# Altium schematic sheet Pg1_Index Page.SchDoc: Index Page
size 431 x 279 mm; Date: Not shown in title block; ApprovedBy: Not shown in title block; CheckedBy: Not shown in title block; Author: Not shown in title block; CompanyName: Not shown in title block; Engineer: Not shown in title block; Organization: Not shown in title block; Address1: Not shown in title block; Address2: Not shown in title block; Address3: Not shown in title block; Address4: Not shown in title block; DocumentNumber: 1; Revision: Use project parameter SCH_Rev; SheetNumber: 1; SheetTotal: 9; PageSetup: Record=PageOptions|CenterHorizontal=True|CenterVertical=True|PrintScale=1.00|XCorrection=1.00|YCorrection=1.00|PrintKind=0|BorderSize=5000000|LeftOffset=0|BottomOffset=0|Orientation=2|PaperLength=1000|PaperWidth=1000|Scale=100|PaperSource=15|PrintQuality=600|MediaType=1|DitherType=10|PaperKind=Letter|PrintScaleMode=1
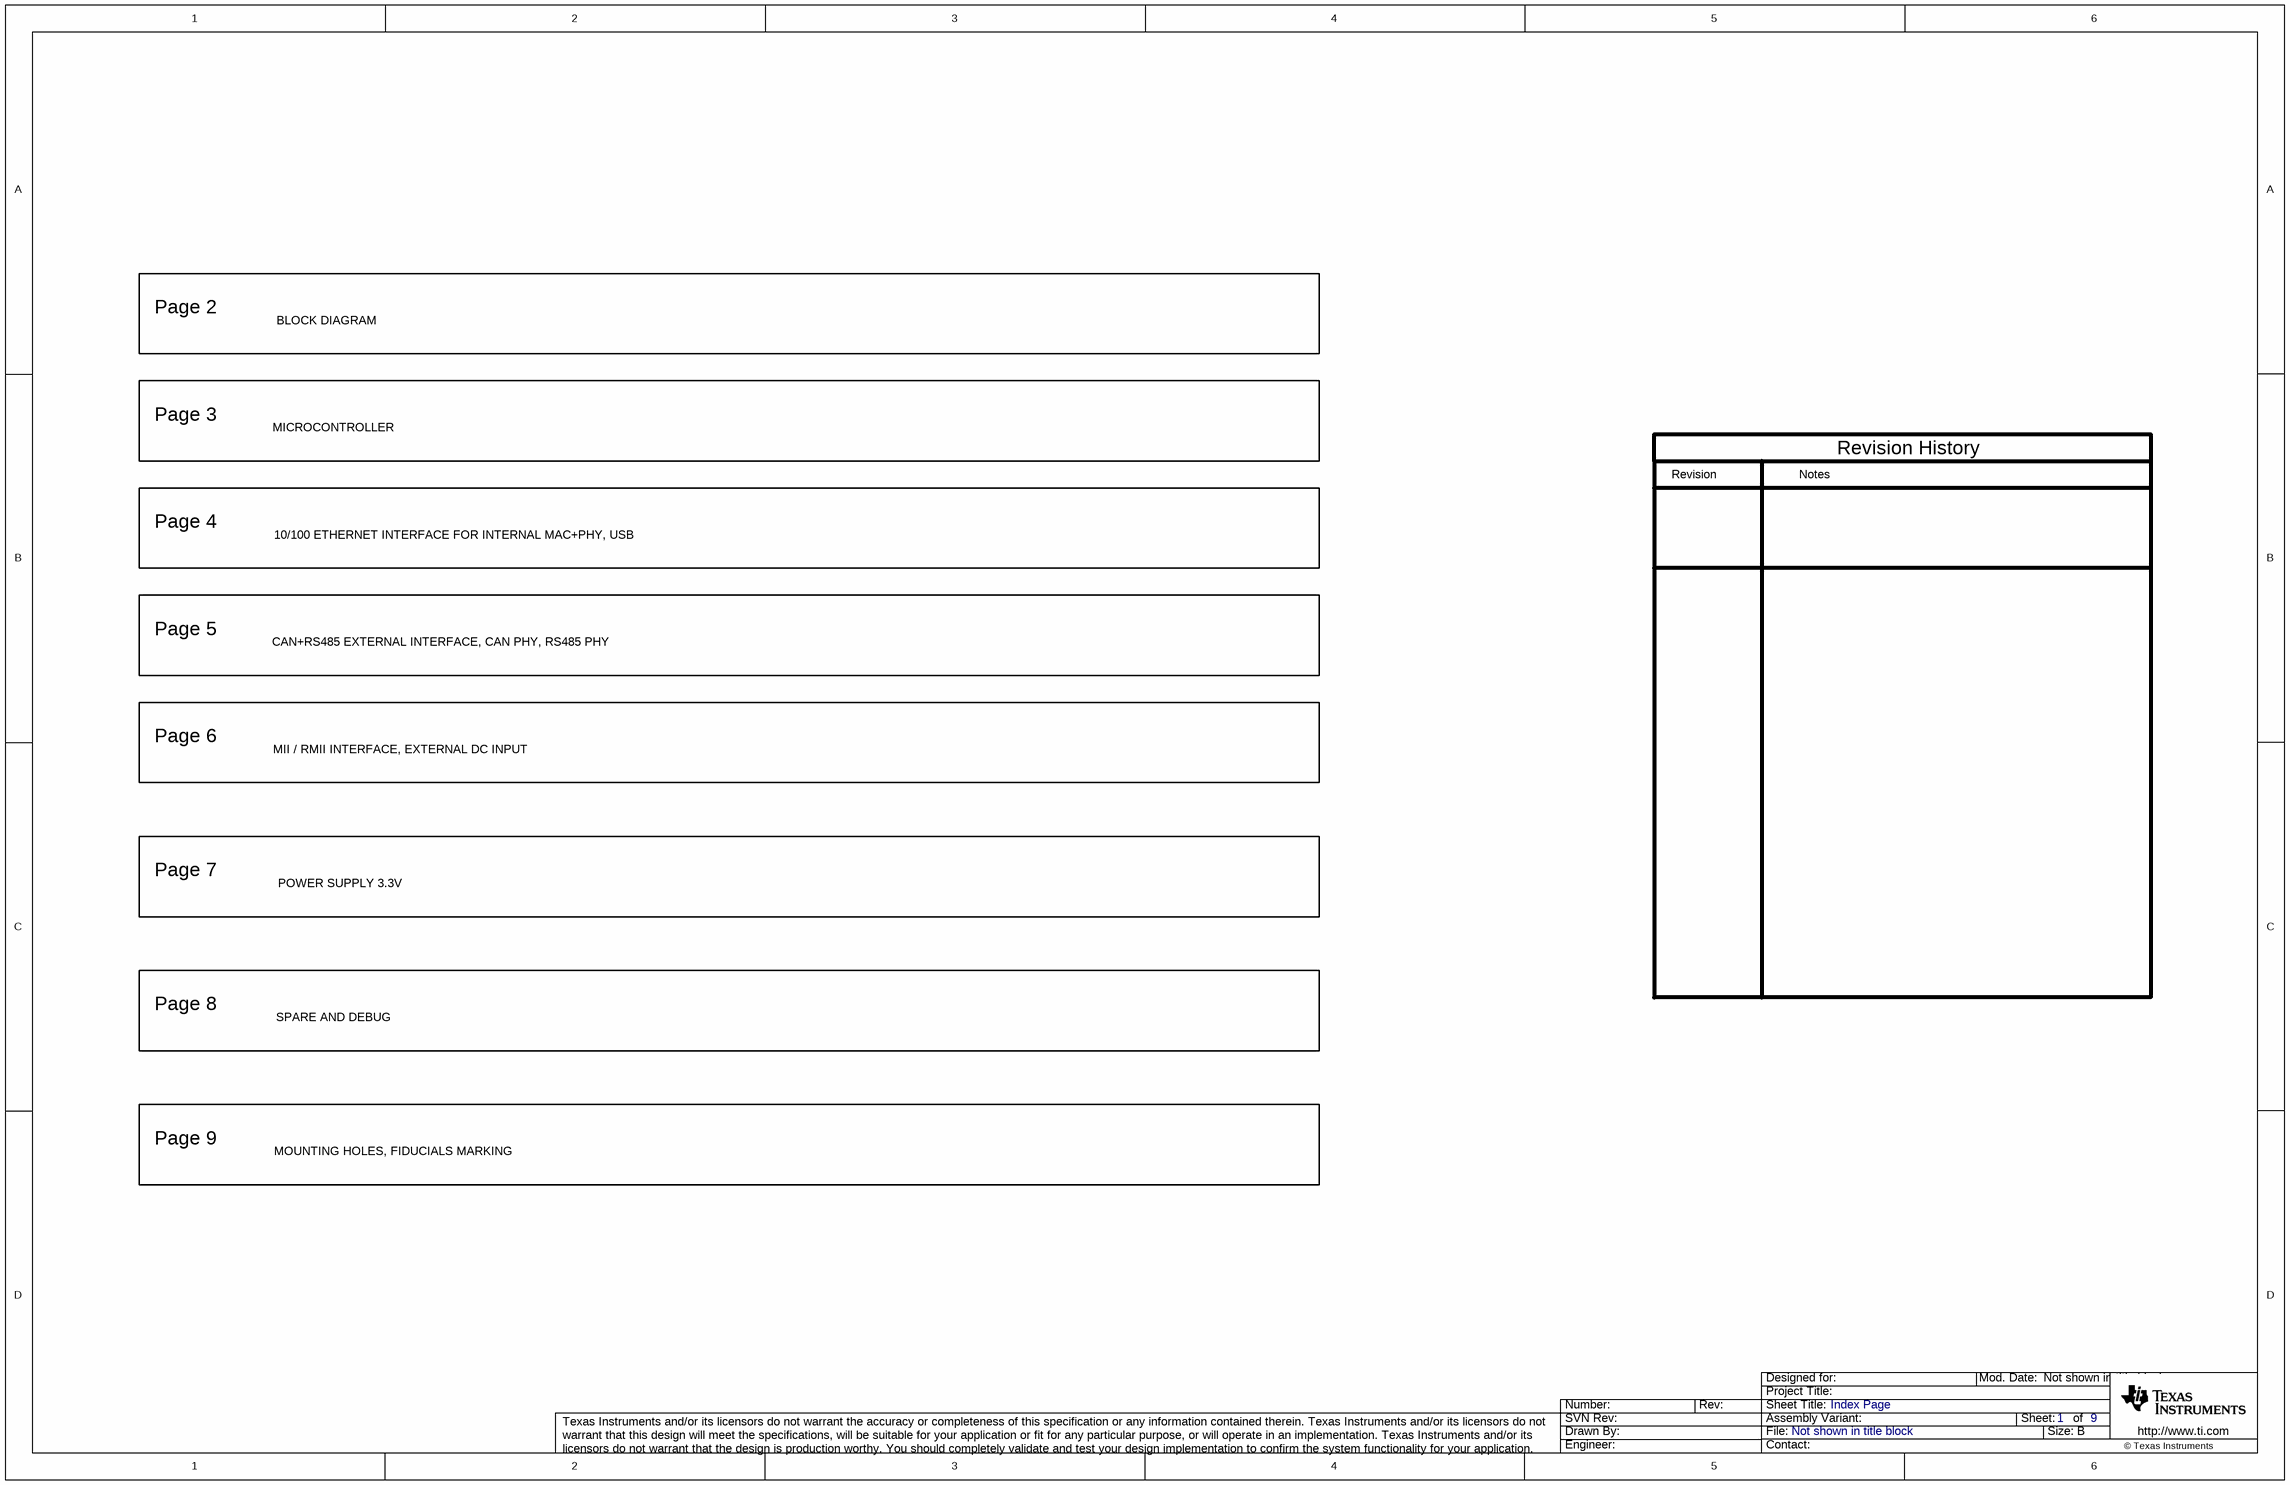
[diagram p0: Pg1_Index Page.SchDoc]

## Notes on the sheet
- Page 2
- BLOCK DIAGRAM
- Page 3
- MICROCONTROLLER
- Revision
- Notes
- Revision History
- Page 4
- 10/100 ETHERNET INTERFACE FOR INTERNAL MAC+PHY, USB
- Page 5
- CAN+RS485 EXTERNAL INTERFACE, CAN PHY, RS485 PHY
- Page 6
- MII / RMII INTERFACE, EXTERNAL DC INPUT
- Page 7
- POWER SUPPLY 3.3V
- Page 8
- SPARE AND DEBUG
- Page 9
- MOUNTING HOLES, FIDUCIALS MARKING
